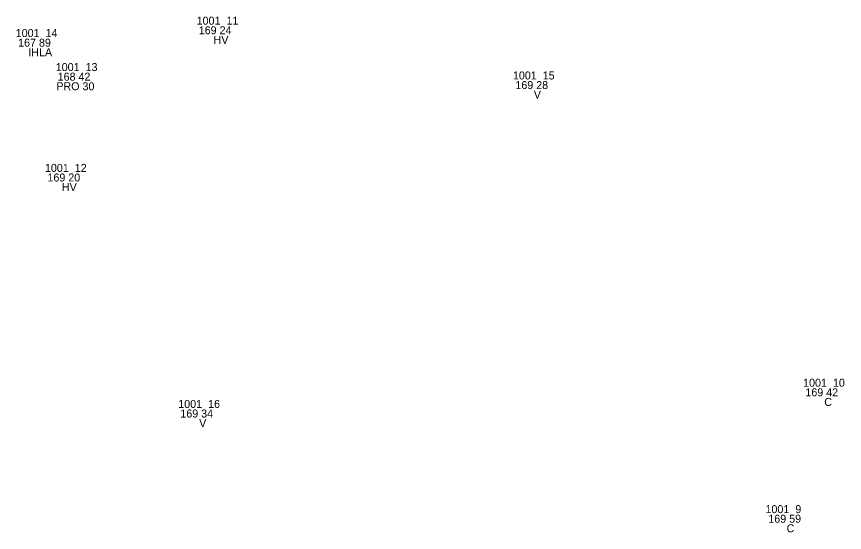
# Model space of a CAD drawing. Extents: x -607541 to -607268, y -1195145 to -1195000.
# Drawn here: x -607540.56 to -607519.88, y -1195012.44 to -1194999.55 of the extents above; entities that cross this region are included whole.
import ezdxf

# ---------------------------------------------------------------- set-up
doc = ezdxf.new("R2010")
doc.units = 0
for name, color, linetype in [('Vrstva 20', 7, 'Continuous'), ('Vrstva 21', 7, 'Continuous'), ('Vrstva 22', 7, 'Continuous'), ('Vrstva 23', 7, 'Continuous'), ('Vrstva 24', 7, 'Continuous')]:
    doc.layers.add(name, color=color, linetype=linetype)

msp = doc.modelspace()

# ---------------------------------------------------------------- linework, layer by layer
at = {"layer": 'Vrstva 20'}
for p, q in [((-607535.39, -1194999.89), (-607535.39, -1194999.89)), ((-607539.91, -1195000.2), (-607539.91, -1195000.2)), ((-607538.91, -1195001.05), (-607538.91, -1195001.05)), ((-607527.49, -1195001.26), (-607527.49, -1195001.26)), ((-607539.18, -1195003.57), (-607539.18, -1195003.57)), ((-607520.24, -1195008.94), (-607520.24, -1195008.94)), ((-607535.85, -1195009.47), (-607535.85, -1195009.47)), ((-607521.18, -1195012.1), (-607521.18, -1195012.1))]:
    msp.add_line(p, q, dxfattribs=at)

# ---------------------------------------------------------------- texts
at = {"layer": 'Vrstva 21'}
for p in [(-607536.061, -1194999.75), (-607540.581, -1195000.06), (-607539.581, -1195000.91), (-607528.161, -1195001.12), (-607539.851, -1195003.43), (-607520.911, -1195008.8), (-607536.521, -1195009.33), (-607521.851, -1195011.96)]:
    msp.add_text('1001 ', height=0.2, dxfattribs=at).set_placement(p)
at = {"layer": 'Vrstva 22'}
for s, p in [(' 11', (-607535.39, -1194999.75)), (' 14', (-607539.91, -1195000.06)), (' 13', (-607538.91, -1195000.91)), (' 15', (-607527.49, -1195001.12)), (' 12', (-607539.18, -1195003.43)), (' 10', (-607520.24, -1195008.8)), (' 16', (-607535.85, -1195009.33)), (' 9', (-607521.18, -1195011.96))]:
    msp.add_text(s, height=0.2, dxfattribs=at).set_placement(p)
at = {"layer": 'Vrstva 23'}
for s, p in [('169 24 ', (-607536.009, -1194999.99)), ('167 89 ', (-607540.521, -1195000.3)), ('168 42 ', (-607539.534, -1195001.15)), ('169 28 ', (-607528.099, -1195001.36)), ('169 20 ', (-607539.788, -1195003.67)), ('169 42 ', (-607520.854, -1195009.04)), ('169 34 ', (-607536.469, -1195009.57)), ('169 59 ', (-607521.78, -1195012.2))]:
    msp.add_text(s, height=0.2, dxfattribs=at).set_placement(p)
at = {"layer": 'Vrstva 24'}
for s, p in [('HV ', (-607535.638, -1195000.23)), ('IHLA ', (-607540.267, -1195000.54)), ('PRO 30 ', (-607539.567, -1195001.39)), ('V ', (-607527.638, -1195001.6)), ('HV ', (-607539.428, -1195003.91)), ('C ', (-607520.383, -1195009.28)), ('V ', (-607535.998, -1195009.81)), ('C ', (-607521.323, -1195012.44))]:
    msp.add_text(s, height=0.2, dxfattribs=at).set_placement(p)

doc.saveas('drawing.dxf')
